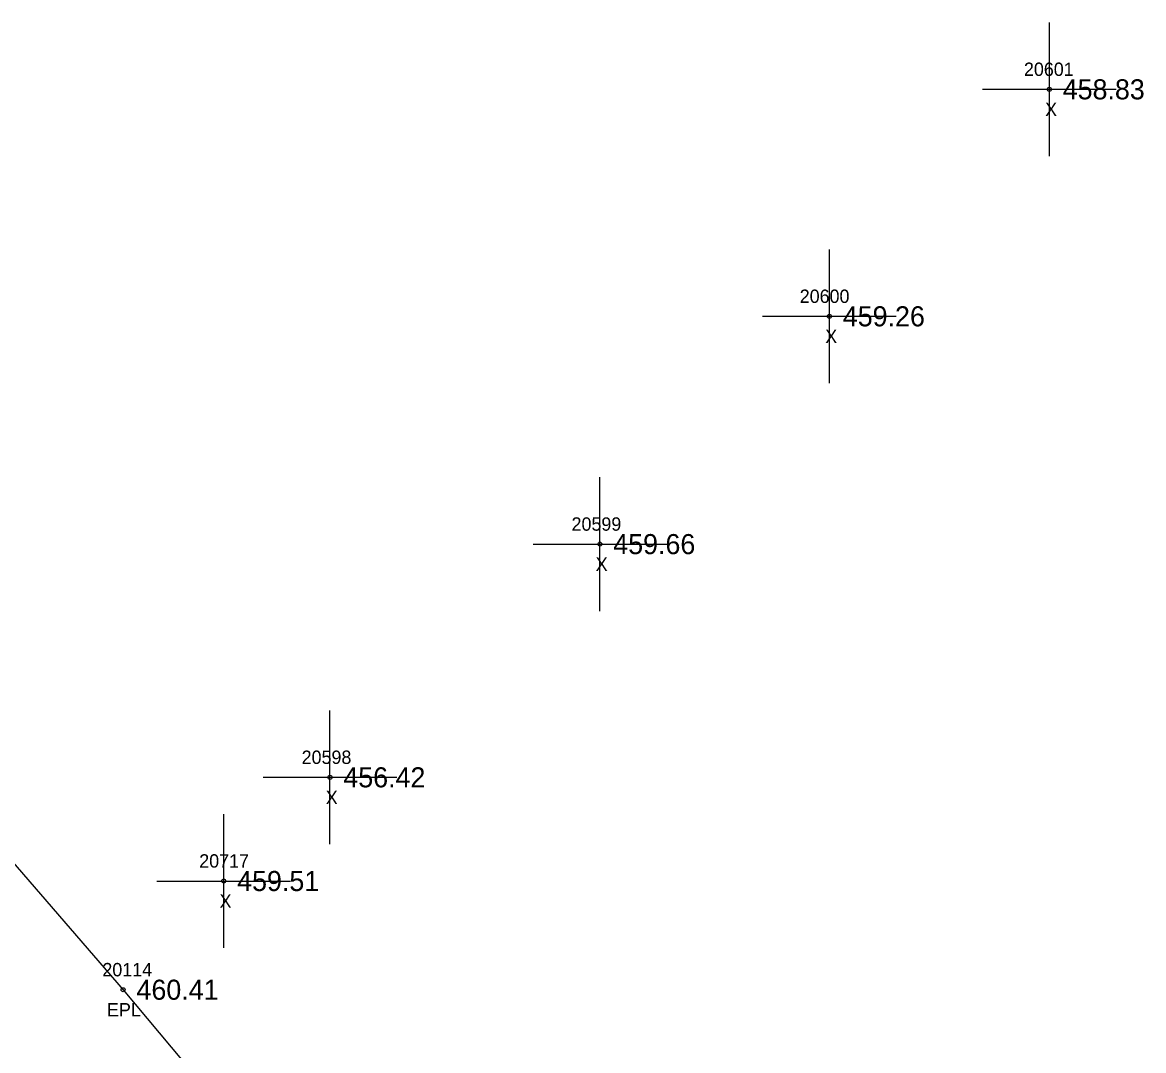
# Model space of a CAD drawing. Extents: x 1747760 to 1751131, y 649333 to 653784.
# Drawn here: x 1749323.7 to 1749407.6, y 651202.5 to 651279.3 of the extents above; entities that cross this region are included whole.
import ezdxf

# ---------------------------------------------------------------- set-up
doc = ezdxf.new("R2010")
doc.units = 0
for name, color, linetype in [('RD_EX_Misc', 7, 'Continuous'), ('RD_EX_Misc_txCode', 7, 'Continuous'), ('RD_EX_Road', 7, 'Continuous'), ('RD_EX_Road_txCode', 7, 'Continuous'), ('RD_EX_TX_Misc_ELEV', 7, 'Continuous'), ('RD_EX_TX_Road_ELEV', 7, 'Continuous'), ('RD_SMD_Locator', 7, 'Continuous')]:
    doc.layers.add(name, color=color, linetype=linetype)

msp = doc.modelspace()

# ---------------------------------------------------------------- linework, layer by layer
at = {"layer": 'RD_EX_Misc'}
for p, q in [((1749400.538, 651269.339), (1749400.538, 651279.339)), ((1749395.538, 651274.339), (1749405.538, 651274.339)), ((1749384.095, 651252.373), (1749384.095, 651262.373)), ((1749379.095, 651257.373), (1749389.095, 651257.373)), ((1749366.93, 651235.346), (1749366.93, 651245.346)), ((1749361.93, 651240.346), (1749371.93, 651240.346)), ((1749346.746, 651217.914), (1749346.746, 651227.914)), ((1749341.746, 651222.914), (1749351.746, 651222.914)), ((1749338.807, 651210.165), (1749338.807, 651220.165)), ((1749333.807, 651215.165), (1749343.807, 651215.165))]:
    msp.add_line(p, q, dxfattribs=at)
at = {"layer": 'RD_EX_Road'}
msp.add_lwpolyline([(1749251.231, 651263.495), (1749260.448, 651269.918), (1749270.704, 651277.064), (1749331.28, 651207.039), (1749394.892, 651131.098)], dxfattribs=at)
at = {"layer": 'RD_SMD_Locator'}
for centre in [(1749400.538, 651274.339), (1749384.095, 651257.373), (1749366.93, 651240.346), (1749346.746, 651222.914), (1749338.807, 651215.165), (1749331.28, 651207.039)]:
    msp.add_circle(centre, 0.15, dxfattribs=at)

# ---------------------------------------------------------------- texts
at = {"layer": 'RD_EX_Misc_txCode'}
for s, p in [('20601', (1749398.64, 651275.339)), ('X', (1749400.223, 651272.339)), ('20600', (1749381.874, 651258.373)), ('X', (1749383.78, 651255.373)), ('20599', (1749364.811, 651241.346)), ('X', (1749366.615, 651238.346)), ('20598', (1749344.628, 651223.914)), ('X', (1749346.431, 651220.914)), ('20717', (1749336.972, 651216.165)), ('X', (1749338.492, 651213.165))]:
    msp.add_text(s, height=1, dxfattribs=at).set_placement(p)
at = {"layer": 'RD_EX_Road_txCode'}
for s, p in [('20114', (1749329.728, 651208.039)), ('EPL', (1749330.075, 651205.039))]:
    msp.add_text(s, height=1, dxfattribs=at).set_placement(p)
at = {"layer": 'RD_EX_TX_Misc_ELEV'}
for s, p in [('458.83', (1749401.538, 651273.589)), ('459.26', (1749385.095, 651256.623)), ('459.66', (1749367.93, 651239.596)), ('456.42', (1749347.746, 651222.164)), ('459.51', (1749339.807, 651214.415))]:
    msp.add_text(s, height=1.5, dxfattribs=at).set_placement(p)
at = {"layer": 'RD_EX_TX_Road_ELEV'}
msp.add_text('460.41', height=1.5, dxfattribs=at).set_placement((1749332.28, 651206.289))

doc.saveas('drawing.dxf')
